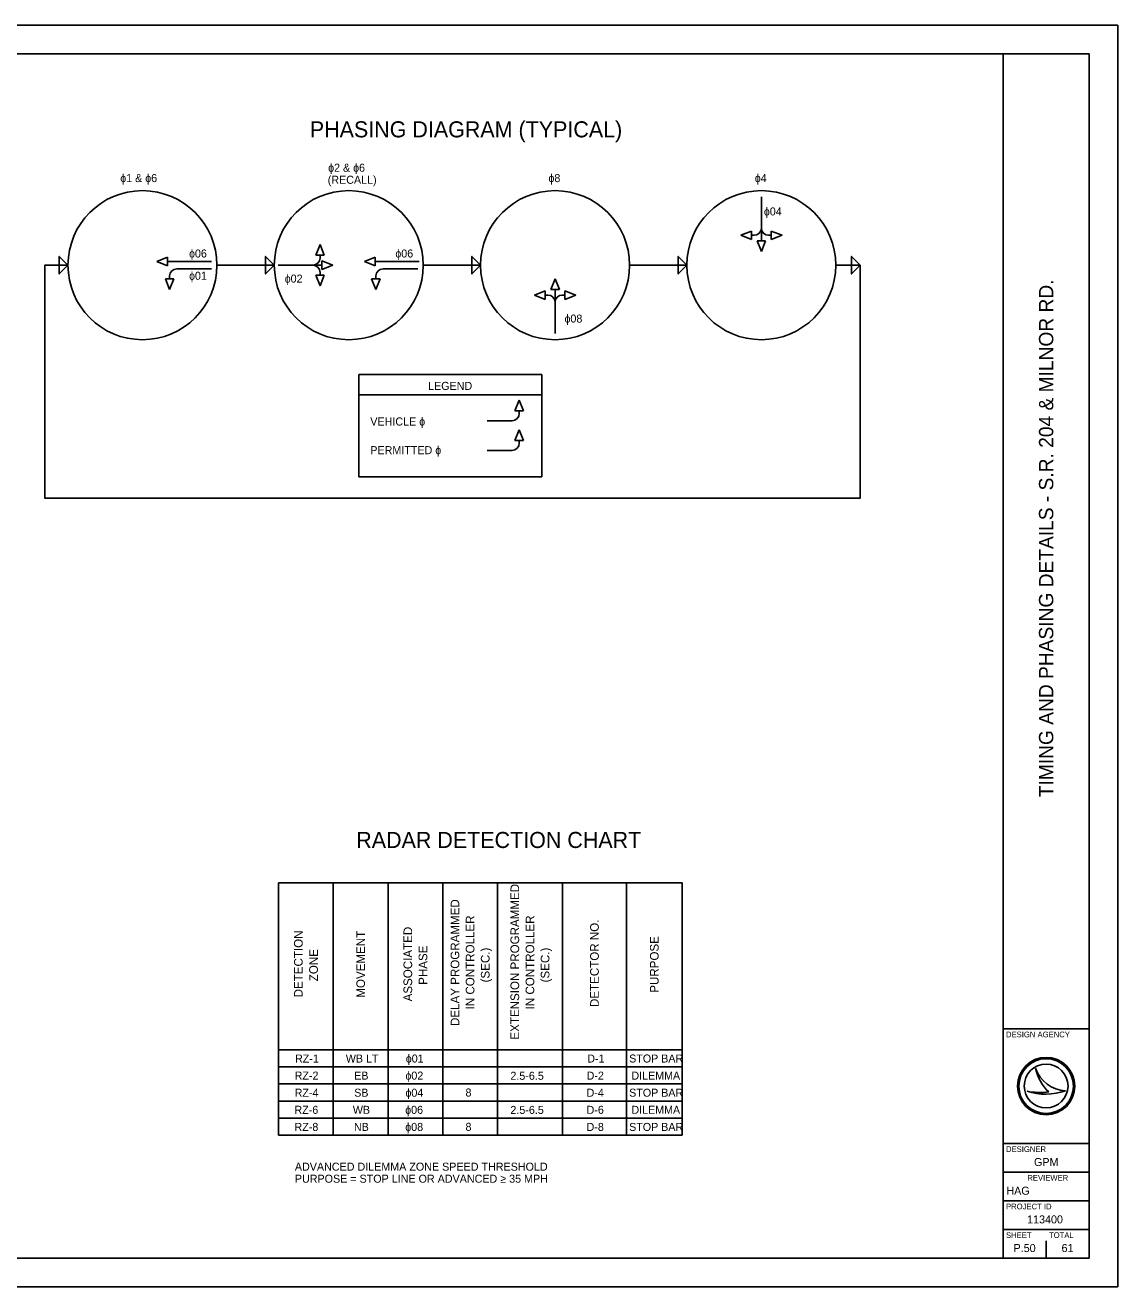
# Model space of a CAD drawing. Extents: x 0 to 680, y 0 to 440.
# Drawn here: x 298.8 to 680, y 0 to 440 of the extents above; entities that cross this region are included whole.
import ezdxf

# ---------------------------------------------------------------- set-up
doc = ezdxf.new("R2010")
doc.units = 0
for name, color, linetype in [('SG_P_Text', 7, 'Continuous'), ('SH_Border', 7, 'Continuous'), ('SH_Cut_Line', 7, 'Continuous'), ('SH_Data', 7, 'Continuous'), ('SH_Text', 7, 'Continuous')]:
    doc.layers.add(name, color=color, linetype=linetype)

msp = doc.modelspace()

# ---------------------------------------------------------------- linework, layer by layer
at = {"layer": 'SG_P_Text'}
for p, q in [((385.67, 356.31), (365.67, 356.31)), ((457.66, 356.31), (437.66, 356.31)), ((529.64, 356.31), (509.64, 356.31)), ((415.18, 311.14), (478.99, 311.14)), ((387.18, 140.84), (527.98, 140.84)), ((387.18, 140.84), (387.18, 52.84)), ((406.27, 140.84), (406.27, 52.84)), ((425.36, 140.84), (425.36, 52.84)), ((444.45, 140.84), (444.45, 52.84)), ((463.54, 140.84), (463.54, 52.84)), ((486.21, 140.84), (486.21, 52.84)), ((508.59, 140.84), (508.59, 52.84)), ((527.98, 140.84), (527.98, 52.84)), ((387.18, 82.67), (527.98, 82.67)), ((387.18, 76.7), (527.98, 76.7)), ((387.18, 70.74), (527.98, 70.74)), ((387.18, 64.77), (527.98, 64.77)), ((387.18, 58.8), (527.98, 58.8)), ((387.18, 52.84), (406.27, 52.84)), ((387.18, 52.84), (527.98, 52.84)), ((406.27, 52.84), (425.36, 52.84)), ((425.36, 52.84), (456.09, 52.84)), ((425.36, 52.84), (444.45, 52.84)), ((444.45, 52.84), (463.54, 52.84)), ((463.54, 52.84), (486.21, 52.84)), ((486.21, 52.84), (508.59, 52.84)), ((508.59, 52.84), (527.98, 52.84))]:
    msp.add_line(p, q, dxfattribs=at)
for points in [[(313.69, 356.31), (310.66, 359.34), (310.66, 353.28)], [(385.67, 356.31), (382.64, 359.34), (382.64, 353.28)], [(457.66, 356.31), (454.63, 359.34), (454.62, 353.28)], [(529.64, 356.31), (526.61, 359.34), (526.61, 353.28)], [(590.15, 356.31), (587.12, 359.34), (587.12, 353.28)]]:
    msp.add_lwpolyline(points, close=True, dxfattribs=at)
for points in [[(581.63, 356.31), (590.15, 356.31), (590.15, 275.08), (313.69, 275.08), (305.57, 275.08), (305.57, 356.31), (313.69, 356.31)], [(478.99, 282.45), (478.99, 318.14), (415.23, 318.14), (415.23, 282.45)]]:
    msp.add_lwpolyline(points, dxfattribs=at)
for centre in [(339.68, 356.31), (411.67, 356.31), (483.65, 356.31), (555.63, 356.31)]:
    msp.add_circle(centre, 25.99, dxfattribs=at)
at = {"layer": 'SH_Border'}
for p, q in [((640, 10), (640, 430)), ((640, 90), (670, 90)), ((640, 50), (670, 50)), ((640, 40), (670, 40)), ((640, 30), (670, 30)), ((640, 20), (670, 20))]:
    msp.add_line(p, q, dxfattribs=at)
msp.add_lwpolyline([(30, 430), (670, 430), (670, 10), (30, 10)], close=True, dxfattribs=at)
at = {"layer": 'SH_Cut_Line'}
msp.add_lwpolyline([(0, 0), (680, 0), (680, 440), (0, 440)], close=True, dxfattribs=at)
at = {"layer": 'SH_Data'}
for p, q in [((651.35, 76.19), (651.35, 76.19)), ((648.34, 68.19), (648.34, 68.19)), ((655, 70), (655, 70)), ((661.75, 68.37), (661.75, 68.37)), ((647.5, 13.5), (647.5, 13.5)), ((655, 10), (655, 16))]:
    msp.add_line(p, q, dxfattribs=at)
for radius in [10, 9.54, 9.54, 7.64]:
    msp.add_circle((655, 70), radius, dxfattribs=at)
for centre, radius, start, end in [((662.32, 79.95), 11.6, 198.9257, 198.9319), ((666.93, 79.4), 15.91, 191.6379, 191.6421), ((662.32, 79.95), 11.6, 198.9319, 267.1657), ((666.93, 79.4), 15.91, 191.6421, 226.0947), ((654.79, 87.4), 20.26, 251.4576, 290.0832), ((652.96, 93.09), 25.32, 259.4964, 259.4995), ((654.79, 87.4), 20.26, 251.4527, 251.4576), ((652.96, 93.09), 25.32, 259.4995, 276.6672)]:
    msp.add_arc(centre, radius, start, end, dxfattribs=at)
at = {"layer": 'SH_Text'}
for p, q in [((555.63, 364.85), (555.63, 380.17)), ((552.18, 368.23), (548.43, 366.73)), ((548.43, 366.73), (552.18, 365.23)), ((552.18, 366.73), (552.18, 368.23)), ((552.18, 365.23), (552.18, 366.73)), ((552.18, 366.73), (553.13, 366.73)), ((559.09, 366.73), (558.13, 366.73)), ((559.09, 366.73), (559.09, 368.23)), ((559.09, 368.23), (562.84, 366.73)), ((562.84, 366.73), (559.09, 365.23)), ((559.09, 365.23), (559.09, 366.73)), ((400.13, 359.76), (401.63, 363.51)), ((401.63, 363.51), (403.13, 359.76)), ((555.63, 361.1), (554.13, 364.85)), ((554.13, 364.85), (555.63, 364.85)), ((555.63, 364.85), (557.13, 364.85)), ((557.13, 364.85), (555.63, 361.1)), ((348.47, 359.08), (344.72, 357.58)), ((344.72, 357.58), (348.47, 356.08)), ((348.47, 357.58), (348.47, 359.08)), ((348.47, 357.58), (363.79, 357.58)), ((348.47, 356.08), (348.47, 357.58)), ((401.63, 359.76), (400.13, 359.76)), ((403.13, 359.76), (401.63, 359.76)), ((401.63, 358.81), (401.63, 359.76)), ((402.32, 356.31), (402.32, 357.81)), ((402.32, 357.81), (406.07, 356.31)), ((420.9, 359.08), (417.15, 357.58)), ((417.15, 357.58), (420.9, 356.08)), ((420.9, 357.58), (420.9, 359.08)), ((420.9, 357.58), (436.22, 357.58)), ((420.9, 356.08), (420.9, 357.58)), ((349.16, 351.59), (349.16, 352.54)), ((351.66, 355.04), (363.79, 355.04)), ((402.32, 356.31), (387.01, 356.31)), ((387.01, 356.31), (399.13, 356.31)), ((387.01, 356.31), (399.13, 356.31)), ((401.63, 352.86), (400.13, 352.86)), ((400.13, 352.86), (401.63, 349.11)), ((401.63, 353.81), (401.63, 352.86)), ((401.63, 349.11), (403.13, 352.86)), ((403.13, 352.86), (401.63, 352.86)), ((406.07, 356.31), (402.32, 354.81)), ((402.32, 354.81), (402.32, 356.31)), ((421.14, 351.59), (421.14, 352.54)), ((423.64, 355.04), (435.77, 355.04)), ((349.16, 347.84), (347.66, 351.59)), ((347.66, 351.59), (349.16, 351.59)), ((349.16, 351.59), (350.66, 351.59)), ((350.66, 351.59), (349.16, 347.84)), ((421.14, 351.59), (419.64, 351.59)), ((419.64, 351.59), (421.14, 347.84)), ((421.14, 347.84), (422.64, 351.59)), ((422.64, 351.59), (421.14, 351.59)), ((482.15, 347.77), (483.65, 351.52)), ((483.65, 347.77), (482.15, 347.77)), ((483.65, 351.52), (485.15, 347.77)), ((485.15, 347.77), (483.65, 347.77)), ((483.65, 347.77), (483.65, 332.45)), ((476.45, 345.89), (480.2, 347.39)), ((480.2, 344.39), (476.45, 345.89)), ((480.2, 347.39), (480.2, 345.89)), ((480.2, 345.89), (481.15, 345.89)), ((480.2, 345.89), (480.2, 344.39)), ((487.1, 345.89), (486.15, 345.89)), ((490.85, 345.89), (487.1, 347.39)), ((487.1, 347.39), (487.1, 345.89)), ((487.1, 345.89), (487.1, 344.39)), ((487.1, 344.39), (490.85, 345.89)), ((471.15, 309.27), (469.65, 305.52)), ((472.65, 305.52), (471.15, 309.27)), ((469.65, 305.52), (471.15, 305.52)), ((471.15, 305.52), (471.15, 304.57)), ((471.15, 305.52), (472.65, 305.52)), ((468.65, 302.07), (459.9, 302.07)), ((471.15, 298.94), (469.65, 295.19)), ((469.65, 295.19), (471.15, 295.19)), ((472.65, 295.19), (471.15, 298.94)), ((471.15, 295.19), (472.65, 295.19)), ((471.15, 295.19), (471.15, 294.23)), ((468.65, 291.73), (459.9, 291.73)), ((415.23, 282.45), (478.99, 282.45))]:
    msp.add_line(p, q, dxfattribs=at)
for centre, start, end in [((553.13, 369.23), 270, 360), ((558.13, 369.23), 180, 270), ((399.13, 358.81), 270, 0), ((351.66, 352.54), 90, 180), ((399.13, 353.81), 360, 90), ((423.64, 352.54), 90, 180), ((481.15, 343.39), 0, 90), ((486.15, 343.39), 90, 180), ((468.65, 304.57), 270, 360), ((468.65, 294.23), 270, 360)]:
    msp.add_arc(centre, 2.5, start, end, dxfattribs=at)

# ---------------------------------------------------------------- texts
at = {"layer": 'SG_P_Text'}
for s, height, p in [('PHASING DIAGRAM (TYPICAL)', 5.6, (398.07, 400.89)), ('ɸ2 & ɸ6', 2.8, (404.47, 388.9)), ('ɸ1 & ɸ6', 2.8, (331.93, 385.29)), ('(RECALL)', 2.8, (404.32, 384.7)), ('ɸ8', 2.8, (481.35, 385.29)), ('ɸ4', 2.8, (553.34, 385.29)), ('ɸ04', 2.8, (556.52, 373.66)), ('ɸ06', 2.8, (355.93, 358.98)), ('ɸ06', 2.8, (427.92, 358.98)), ('ɸ01', 2.8, (355.93, 351.22)), ('ɸ02', 2.8, (389.32, 350.23)), ('ɸ08', 2.8, (486.94, 336.29)), ('LEGEND', 2.8, (439.34, 312.81)), ('VEHICLE ɸ', 2.8, (419.18, 300.39)), ('PERMITTED ɸ', 2.8, (419.18, 290.39)), ('RADAR DETECTION CHART', 5.6, (414.28, 153.04)), ('RZ-1', 2.8, (392.9, 78.21)), ('WB LT', 2.787, (410.63, 78.22)), ('ɸ01', 2.8, (431.57, 78.21)), ('D-1', 2.787, (494.9, 78.22)), ('STOP BAR', 2.787, (509.51, 78.22)), ('RZ-2', 2.8, (392.77, 72.25)), ('EB', 2.787, (413.57, 72.25)), ('ɸ02', 2.8, (431.44, 72.25)), ('D-2', 2.787, (494.67, 72.25)), ('DILEMMA', 2.787, (510.3, 72.25)), ('RZ-4', 2.8, (392.78, 66.28)), ('SB', 2.787, (413.57, 66.29)), ('ɸ04', 2.8, (431.45, 66.28)), ('D-4', 2.787, (494.66, 66.29)), ('STOP BAR', 2.787, (509.51, 66.29)), ('RZ-6', 2.8, (392.7, 60.31)), ('WB', 2.787, (413.09, 60.32)), ('ɸ06', 2.8, (431.36, 60.31)), ('D-6', 2.787, (494.66, 60.32)), ('DILEMMA', 2.787, (510.3, 60.32)), ('ɸ08', 2.8, (431.38, 54.35)), ('RZ-8', 2.8, (392.72, 54.35)), ('NB', 2.787, (413.48, 54.36)), ('D-8', 2.787, (494.66, 54.36)), ('STOP BAR', 2.787, (509.51, 54.36)), ('ADVANCED DILEMMA ZONE SPEED THRESHOLD', 2.8, (392.85, 40.49)), ('PURPOSE = STOP LINE OR ADVANCED ≥ 35 MPH', 2.8, (392.85, 36.29))]:
    msp.add_text(s, height=height, dxfattribs=at).set_placement(p)
for s, height, p in [('EXTENSION PROGRAMMED', 3.0188, (471.11, 86.22)), ('DELAY PROGRAMMED', 3.0188, (450.23, 90.96)), (' IN CONTROLLER', 3.0188, (455.51, 95.63)), (' IN CONTROLLER', 3.0188, (476.39, 95.63)), ('DETECTOR NO.', 3.0188, (498.91, 97.57)), ('DETECTION', 3.019, (395.59, 100.94)), ('MOVEMENT', 3.019, (417.33, 100.82)), ('ASSOCIATED', 3.019, (433.78, 99.54)), ('PHASE', 3.019, (439.06, 105.31)), ('PURPOSE', 3.019, (519.79, 102.56)), ('ZONE', 3.019, (400.88, 106.57)), ('(SEC.)', 3.019, (460.79, 106.16)), ('(SEC.)', 3.019, (481.67, 106.16))]:
    msp.add_text(s, height=height, rotation=90, dxfattribs=at).set_placement(p)
at = {"layer": 'SH_Data'}
msp.add_text('TIMING AND PHASING DETAILS - S.R. 204 & MILNOR RD.', height=5, rotation=90, dxfattribs=at).set_placement((657.5, 170.76))
for s, height, p in [('DESIGN AGENCY', 2, (641, 87)), ('DESIGNER', 2, (641, 47)), ('GPM', 2.8, (650.77, 42.1)), ('REVIEWER', 2, (648.44, 37)), ('HAG', 2.8, (641.13, 32.1)), ('PROJECT ID', 2, (641, 27)), ('113400', 2.8, (648.37, 22.1)), ('SHEET', 2, (641, 17)), ('TOTAL', 2, (656, 17)), ('P.50', 2.8, (643.64, 12.1)), ('61', 2.8, (660.38, 12.1))]:
    msp.add_text(s, height=height, dxfattribs=at).set_placement(p)
at = {"layer": 'SH_Text'}
for s, p in [('2.5-6.5', (468.06, 72.19)), ('8', (452.39, 66.35)), ('2.5-6.5', (468.06, 60.28)), ('8', (452.39, 54.38))]:
    msp.add_text(s, height=2.8, dxfattribs=at).set_placement(p)

doc.saveas('drawing.dxf')
